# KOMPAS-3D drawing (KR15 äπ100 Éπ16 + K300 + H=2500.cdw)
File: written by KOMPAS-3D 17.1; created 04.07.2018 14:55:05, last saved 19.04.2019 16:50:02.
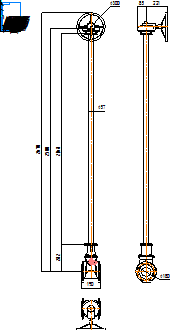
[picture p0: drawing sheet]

Sheet 1: A4, portrait

Title block, sheet 1: name: KR15 Ду100 Ру16 + / K300 + H=2500; material: Внимание! Данный продукт является объектом авторского права ООО «Торговый Дом АДЛ». / Запрещается изменение, копирование, распространение / (в том числе путем копирования на другие сайты и ресурсы в Интернете) / или любое иное использование информации и объектов без предварительного / согласия правообладателя (ООО «Торговый Дом АДЛ»).; mass: 36,7; sheets: 1; organisation: ООО "Торговый дом АДЛ"; sheet format: A4; stored path: \\adlc.lan\data\АДЛ_ПКД\3D-модели\ADL production\Клиновые задвижки серии KR ГРАНАР\Клиновые задвижки KR15 со стационарным удлинением\KOMPAS 2D\KR15 Ду100 Ру16 + K300 + H=2500.cdw

Views: Проекционный вид 6, Спереди 7, Проекционный вид 8
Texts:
  kka
  adl
Dimensions and other numbers on the sheet: 2500; 2168; 2670; 300; 57; 282; 190; 85; 180; 221; 1:1; 1; 36,7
